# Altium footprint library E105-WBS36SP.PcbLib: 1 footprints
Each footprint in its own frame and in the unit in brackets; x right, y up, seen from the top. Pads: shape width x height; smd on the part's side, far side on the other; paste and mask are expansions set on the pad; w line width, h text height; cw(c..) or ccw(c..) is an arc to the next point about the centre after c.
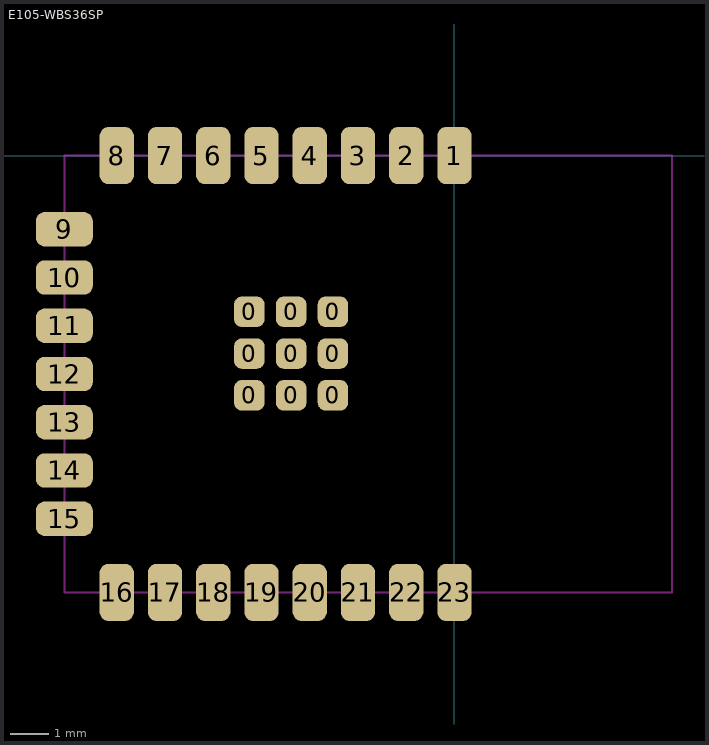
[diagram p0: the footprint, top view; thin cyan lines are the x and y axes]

## E105-WBS36SP [mm]
pads (32):
  rrect50% 0.8x0.8 smd: 0(-5.4,-6.312) 0(-5.4,-5.212) 0(-5.4,-4.112) 0(-4.3,-6.312) 0(-4.3,-5.212) 0(-4.3,-4.112) 0(-3.2,-6.312) 0(-3.2,-5.212) 0(-3.2,-4.112)
  rrect50% 0.9x1.5 smd: 1(0,0) 2(-1.27,0) 3(-2.54,0) 4(-3.81,0) 5(-5.08,0) 6(-6.35,0) 7(-7.62,0) 8(-8.89,0) 16(-8.89,-11.5) 17(-7.62,-11.5) 18(-6.35,-11.5) 19(-5.08,-11.5) 20(-3.81,-11.5) 21(-2.54,-11.5) 22(-1.27,-11.5) 23(0,-11.5)
  rrect50% 1.5x0.9 smd: 9(-10.27,-1.94) 10(-10.27,-3.21) 11(-10.27,-4.48) 12(-10.27,-5.75) 13(-10.27,-7.02) 14(-10.27,-8.29) 15(-10.27,-9.56)
Keep-Out Layer:
  lines w0.05: -10.27,-11.5 5.73,-11.5 5.73,0 -10.27,0 -10.27,-11.5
